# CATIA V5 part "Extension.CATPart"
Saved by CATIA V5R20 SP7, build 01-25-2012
Part number: Extension
Bounding box of the stored display mesh (mm): x -250 to 250, y 0 to 92.944, z 0 to 94.87
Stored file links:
  F:\Travaux\Modélisations\CFAO_2011\MMS\MMS_GR2\AA_OK\tquattrone\Catia\Extension.CATPart
  C:\Users\Tom\Documents\Cours 2A\CFAO\Projet thinkmotion\Aileron_citroen.CATProduct
  F:\Travaux\Modélisations\CFAO_2011\MMS\MMS_GR2\AA_OK\tquattrone\Catia\Bielle 2.CATPart
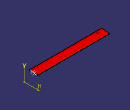
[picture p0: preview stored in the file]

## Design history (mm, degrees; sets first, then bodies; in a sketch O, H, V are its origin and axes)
Parameters
  Diametre_trou_extension = 6 mm
  extrusion_bitoniot = 5 mm
External parameters (linked from other documents)
  External.Diametre_trou_bielle2 = 6 mm
Sketch1 on Plane1, origin (250, 0, 0), H (0, 1, 0), V (0, 0, 1)
  spline S1 through (40.9078, 94.8699) (54.78, 90.6785) (69.3241, 88.0293) (81.4573, 87.0012) (92.9187, 86.8035)
Rib1: profile Sketch1, centre curve Line1, thin wall 0, second thickness 2
Set1
  Plane1 "Plan_bout": linked copy from another document
  Line1 "Courbe_guide": linked copy from another document
  Plane2 "Plan_bielle2/3": linked copy from another document
  Point1 "Point_bielle_22": linked copy from another document
  Plane3 "Plan_sym": linked copy from another document
Body1 (main body)
  Body2
    Sketch2 on Plane2, origin (210, 0, 0), H (0, 1, 0), V (0, 0, 1)
      circle A1 centre (44, 83.0771) radius 3
      point P1 (44, 83.0771)
      reference projected point E1 (44, 83.0771) from Point1
      arc A2 centre (44, 83.0771) radius 5.7822 from (38.4632, 84.7436) to (48.2892, 79.1995) ccw
      line L1 (38.4632, 84.7436) -> (40.5751, 92.9404)
      line L2 (48.2892, 79.1995) -> (56.5868, 88.3778)
      line L3 (56.5868, 88.3778) -> (40.5751, 92.9404)
      radius A1 = 3 {= Diametre_trou_extension /2}
      coincidence: P1 E1
      tangency: L2 A2
    Pad1: profile Sketch2, direction (-1, 0, 0), length 5
    Mirror1: of the body so far, about Plane3
    DatumCurve1
    DatumCurve2
    Sketch3 on face of Rib1, origin (250, 0, 0), H (0, 1, 0), V (0, 0, 1)
      point P1 (59.7185, 88.5846)
      reference projected curve E1 from edge of DatumCurve1
      point P2 (69.6329, 87.0153)
      reference projected curve E2 from edge of DatumCurve2
      distance E1 P1 = 0
      distance P2 E2 = 0
  Assemble1: tool Body2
